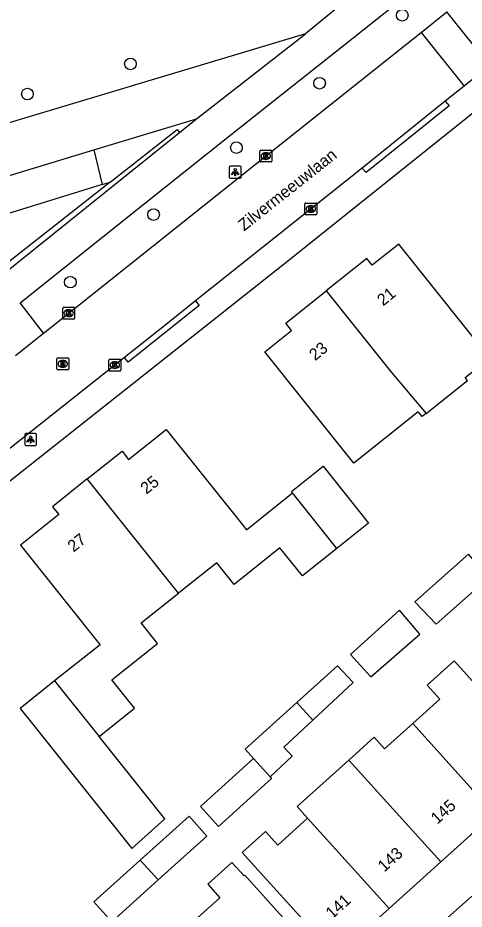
# Model space of a CAD drawing. Extents: x 161772 to 163123, y 383092 to 383917.
# Drawn here: x 162665.1 to 162702.7, y 383567.7 to 383642.9 of the extents above; entities that cross this region are included whole.
import ezdxf

# ---------------------------------------------------------------- set-up
doc = ezdxf.new("R2010")
doc.units = 0
for name, color, linetype in [('IMGEO_Boom', 7, 'Continuous'), ('IMGEO_Groenvoorziening', 7, 'Continuous'), ('IMGEO_Haag', 7, 'Continuous'), ('IMGEO_Kolk', 7, 'Continuous'), ('IMGEO_Lichtpunt', 7, 'Continuous'), ('IMGEO_Openbare_ruimte_label', 7, 'Continuous'), ('IMGEO_Pand', 7, 'Continuous'), ('IMGEO_Pand_nummerreeks', 7, 'Continuous'), ('IMGEO_Rijbaan_lokaal_open', 7, 'Continuous'), ('IMGEO_Rioolput', 7, 'Continuous'), ('IMGEO_Voetpad_open', 7, 'Continuous')]:
    doc.layers.add(name, color=color, linetype=linetype)

msp = doc.modelspace()

# ---------------------------------------------------------------- linework, layer by layer
at = {"layer": 'IMGEO_Boom'}
for centre in [(162697.497, 383643.114), (162674.58, 383639.013), (162690.522, 383637.385), (162665.894, 383636.474), (162683.506, 383631.951), (162676.528, 383626.302), (162669.511, 383620.601)]:
    msp.add_circle(centre, 0.489, dxfattribs=at)
at = {"layer": 'IMGEO_Groenvoorziening'}
for points in [[(162671.488, 383631.764), (162672.208, 383628.835)], [(162672.208, 383628.835), (162648.943, 383621.628)], [(162672.208, 383628.835), (162672.858, 383629.037)]]:
    msp.add_lwpolyline(points, dxfattribs=at)
at = {"layer": 'IMGEO_Haag'}
for points in [[(162672.858, 383629.037), (162678.511, 383633.479), (162678.71, 383633.228)], [(162672.858, 383629.037), (162659.165, 383618.275), (162658.88, 383618.558), (162651.638, 383612.821), (162648.943, 383621.628)]]:
    msp.add_lwpolyline(points, dxfattribs=at)
at = {"layer": 'IMGEO_Kolk'}
for p, q in [((162685.488, 383630.813), (162685.488, 383631.665)), ((162685.563, 383631.739), (162686.415, 383631.739)), ((162685.976, 383631.519), (162686.001, 383631.519)), ((162686.489, 383631.665), (162686.489, 383630.813)), ((162686.415, 383630.739), (162685.563, 383630.739)), ((162685.999, 383630.959), (162685.974, 383630.959)), ((162689.29, 383626.352), (162689.29, 383627.204)), ((162689.365, 383627.278), (162690.217, 383627.278)), ((162689.778, 383627.058), (162689.803, 383627.058)), ((162690.291, 383627.204), (162690.291, 383626.352)), ((162690.217, 383626.278), (162689.365, 383626.278)), ((162689.801, 383626.498), (162689.776, 383626.498)), ((162668.871, 383617.562), (162668.871, 383618.414)), ((162668.946, 383618.488), (162669.798, 383618.488)), ((162669.359, 383618.268), (162669.384, 383618.268)), ((162669.872, 383618.414), (162669.872, 383617.562)), ((162669.382, 383617.708), (162669.357, 383617.708)), ((162669.798, 383617.488), (162668.946, 383617.488)), ((162672.765, 383613.179), (162672.765, 383614.031)), ((162672.84, 383614.105), (162673.692, 383614.105)), ((162673.253, 383613.885), (162673.278, 383613.885)), ((162673.766, 383614.031), (162673.766, 383613.179)), ((162673.692, 383613.105), (162672.84, 383613.105)), ((162673.276, 383613.325), (162673.251, 383613.325))]:
    msp.add_line(p, q, dxfattribs=at)
for points in [[(162685.488, 383630.813), (162685.488, 383631.665)], [(162685.563, 383631.739), (162686.415, 383631.739)], [(162685.809, 383631.439), (162685.932, 383631.439), (162685.932, 383631.288), (162686.062, 383631.439), (162686.226, 383631.439), (162686.08, 383631.288), (162686.233, 383631.039), (162686.081, 383631.039), (162685.996, 383631.203), (162685.932, 383631.136), (162685.932, 383631.039), (162685.809, 383631.039), (162685.809, 383631.439)], [(162686.489, 383631.665), (162686.489, 383630.813)], [(162686.415, 383630.739), (162685.563, 383630.739)], [(162689.29, 383626.352), (162689.29, 383627.204)], [(162689.365, 383627.278), (162690.217, 383627.278)], [(162689.611, 383626.978), (162689.734, 383626.978), (162689.734, 383626.827), (162689.864, 383626.978), (162690.028, 383626.978), (162689.882, 383626.827), (162690.035, 383626.578), (162689.883, 383626.578), (162689.798, 383626.742), (162689.734, 383626.675), (162689.734, 383626.578), (162689.611, 383626.578), (162689.611, 383626.978)], [(162690.291, 383627.204), (162690.291, 383626.352)], [(162690.217, 383626.278), (162689.365, 383626.278)], [(162668.871, 383617.562), (162668.871, 383618.414)], [(162668.946, 383618.488), (162669.798, 383618.488)], [(162669.872, 383618.414), (162669.872, 383617.562)], [(162669.192, 383618.188), (162669.315, 383618.188), (162669.315, 383618.037), (162669.445, 383618.188), (162669.609, 383618.188), (162669.463, 383618.037), (162669.616, 383617.788), (162669.464, 383617.788), (162669.379, 383617.952), (162669.315, 383617.885), (162669.315, 383617.788), (162669.192, 383617.788), (162669.192, 383618.188)], [(162669.798, 383617.488), (162668.946, 383617.488)], [(162672.765, 383613.179), (162672.765, 383614.031)], [(162672.84, 383614.105), (162673.692, 383614.105)], [(162673.086, 383613.805), (162673.209, 383613.805), (162673.209, 383613.654), (162673.339, 383613.805), (162673.503, 383613.805), (162673.357, 383613.654), (162673.51, 383613.405), (162673.358, 383613.405), (162673.273, 383613.569), (162673.209, 383613.502), (162673.209, 383613.405), (162673.086, 383613.405), (162673.086, 383613.805)], [(162673.766, 383614.031), (162673.766, 383613.179)], [(162673.692, 383613.105), (162672.84, 383613.105)]]:
    msp.add_lwpolyline(points, dxfattribs=at)
for centre, start, end in [((162685.565, 383631.663), 91.55205, 178.44795), ((162685.565, 383631.663), 91.55205, 178.44795), ((162686.413, 383631.663), 1.55205, 88.44795), ((162686.413, 383631.663), 1.55205, 88.44795), ((162685.565, 383630.815), 181.55205, 268.44795), ((162685.565, 383630.815), 181.55205, 268.44795), ((162686.413, 383630.815), 271.55205, 358.44795), ((162686.413, 383630.815), 271.55205, 358.44795), ((162689.367, 383627.202), 91.55205, 178.44795), ((162689.367, 383627.202), 91.55205, 178.44795), ((162690.215, 383627.202), 1.55205, 88.44795), ((162690.215, 383627.202), 1.55205, 88.44795), ((162689.367, 383626.354), 181.55205, 268.44795), ((162689.367, 383626.354), 181.55205, 268.44795), ((162690.215, 383626.354), 271.55205, 358.44795), ((162690.215, 383626.354), 271.55205, 358.44795), ((162668.948, 383618.412), 91.55205, 178.44795), ((162668.948, 383618.412), 91.55205, 178.44795), ((162669.796, 383618.412), 1.55205, 88.44795), ((162669.796, 383618.412), 1.55205, 88.44795), ((162668.948, 383617.564), 181.55205, 268.44795), ((162668.948, 383617.564), 181.55205, 268.44795), ((162669.796, 383617.564), 271.55205, 358.44795), ((162669.796, 383617.564), 271.55205, 358.44795), ((162672.842, 383614.029), 91.55205, 178.44795), ((162672.842, 383614.029), 91.55205, 178.44795), ((162673.69, 383614.029), 1.55205, 88.44795), ((162673.69, 383614.029), 1.55205, 88.44795), ((162672.842, 383613.181), 181.55205, 268.44795), ((162672.842, 383613.181), 181.55205, 268.44795), ((162673.69, 383613.181), 271.55205, 358.44795), ((162673.69, 383613.181), 271.55205, 358.44795)]:
    msp.add_arc(centre, 0.0765, start, end, dxfattribs=at)
for centre, major_axis, ratio, start_param, end_param in [((162685.975, 383631.239), (-0.387, 0.002), 0.722429, 4.712389, 7.853982), ((162686, 383631.239), (-0.39, 0.002), 0.717154, 1.570796, 4.712389), ((162689.777, 383626.778), (-0.387, 0.002), 0.722429, 4.712389, 7.853982), ((162689.802, 383626.778), (-0.39, 0.002), 0.717154, 1.570796, 4.712389), ((162669.358, 383617.988), (-0.387, 0.002), 0.722429, 4.712389, 7.853982), ((162669.383, 383617.988), (-0.39, 0.002), 0.717154, 1.570796, 4.712389), ((162673.252, 383613.605), (-0.387, 0.002), 0.722429, 4.712389, 7.853982), ((162673.277, 383613.605), (-0.39, 0.002), 0.717154, 1.570796, 4.712389)]:
    msp.add_ellipse(centre, major_axis=major_axis, ratio=ratio, start_param=start_param, end_param=end_param, dxfattribs=at)
at = {"layer": 'IMGEO_Lichtpunt'}
for p, q in [((162683.815, 383630.381), (162683.007, 383630.381)), ((162683.815, 383630.381), (162683.007, 383630.381)), ((162682.913, 383630.286), (162682.913, 383629.479)), ((162682.913, 383630.286), (162682.913, 383629.479)), ((162683.909, 383629.479), (162683.909, 383630.286)), ((162683.909, 383629.479), (162683.909, 383630.286)), ((162683.007, 383629.385), (162683.815, 383629.385)), ((162683.007, 383629.385), (162683.815, 383629.385)), ((162666.566, 383607.82), (162665.758, 383607.82)), ((162666.566, 383607.82), (162665.758, 383607.82)), ((162665.664, 383607.725), (162665.664, 383606.918)), ((162665.664, 383607.725), (162665.664, 383606.918)), ((162666.66, 383606.918), (162666.66, 383607.725)), ((162666.66, 383606.918), (162666.66, 383607.725)), ((162665.758, 383606.824), (162666.566, 383606.824)), ((162665.758, 383606.824), (162666.566, 383606.824))]:
    msp.add_line(p, q, dxfattribs=at)
for points in [[(162683.287, 383629.95), (162683.326, 383629.922), (162683.138, 383629.66), (162683.1, 383629.687), (162683.287, 383629.95)], [(162683.389, 383629.902), (162683.436, 383629.902), (162683.436, 383629.58), (162683.389, 383629.58), (162683.389, 383629.902)], [(162683.499, 383629.922), (162683.537, 383629.949), (162683.724, 383629.687), (162683.685, 383629.659), (162683.499, 383629.922)], [(162666.038, 383607.389), (162666.077, 383607.361), (162665.889, 383607.099), (162665.851, 383607.126), (162666.038, 383607.389)], [(162666.14, 383607.341), (162666.187, 383607.341), (162666.187, 383607.019), (162666.14, 383607.019), (162666.14, 383607.341)], [(162666.25, 383607.361), (162666.288, 383607.388), (162666.475, 383607.126), (162666.436, 383607.098), (162666.25, 383607.361)]]:
    msp.add_lwpolyline(points, dxfattribs=at)
for centre in [(162683.412, 383630.084), (162666.163, 383607.523)]:
    msp.add_circle(centre, 0.0994, dxfattribs=at)
for centre, start, end in [((162683.007, 383630.286), 90, 180), ((162683.007, 383630.286), 90, 180), ((162683.815, 383630.286), 0, 90), ((162683.815, 383630.286), 0, 90), ((162683.007, 383629.479), 180, 270), ((162683.007, 383629.479), 180, 270), ((162683.815, 383629.479), 270, 0), ((162683.815, 383629.479), 270, 360), ((162665.758, 383607.725), 90, 180), ((162665.758, 383607.725), 90, 180), ((162666.566, 383607.725), 0, 90), ((162666.566, 383607.725), 0, 90), ((162665.758, 383606.918), 180, 270), ((162665.758, 383606.918), 180, 270), ((162666.566, 383606.918), 270, 0), ((162666.566, 383606.918), 270, 360)]:
    msp.add_arc(centre, 0.0946, start, end, dxfattribs=at)
at = {"layer": 'IMGEO_Pand'}
for points in [[(162699.5, 383609.522), (162702.994, 383612.309), (162702.801, 383612.552), (162704.869, 383614.201), (162700.315, 383619.91), (162697.198, 383623.819), (162694.961, 383622.035), (162694.508, 383622.602), (162691.089, 383619.875)], [(162699.5, 383609.522), (162699.169, 383609.258), (162698.841, 383609.669), (162693.401, 383605.33), (162689.023, 383610.82), (162685.905, 383614.729), (162688.164, 383616.531), (162687.671, 383617.149), (162691.089, 383619.875)], [(162691.089, 383619.875), (162696.576, 383612.99), (162699.5, 383609.522)], [(162670.933, 383604.001), (162673.871, 383606.345), (162674.424, 383605.651), (162677.598, 383608.183), (162684.055, 383600.086), (162684.348, 383599.715), (162688.246, 383602.823)], [(162688.246, 383602.823), (162688.146, 383602.948), (162690.815, 383605.076), (162694.653, 383600.264), (162691.984, 383598.136)], [(162670.933, 383604.001), (162667.996, 383601.659), (162668.533, 383600.986), (162665.313, 383598.418), (162671.756, 383590.339), (162672.015, 383590.01), (162668.189, 383586.96)], [(162678.624, 383594.357), (162670.933, 383604.001)], [(162691.984, 383598.136), (162688.246, 383602.823)], [(162691.984, 383598.136), (162689.071, 383595.813), (162687.18, 383598.184), (162683.312, 383595.1), (162681.852, 383596.931), (162678.624, 383594.357)], [(162698.554, 383593.623), (162700.362, 383591.738), (162704.799, 383595.691), (162703.063, 383597.64), (162698.554, 383593.623)], [(162671.933, 383582.264), (162674.922, 383584.647), (162673.011, 383587.044), (162676.861, 383590.114), (162675.478, 383591.848), (162678.624, 383594.357)], [(162693.12, 383589.196), (162694.834, 383587.297), (162698.965, 383590.915), (162697.248, 383592.922), (162693.12, 383589.196)], [(162689.947, 383583.652), (162693.34, 383586.832), (162692.038, 383588.221), (162688.61, 383585.134)], [(162709.795, 383579.86), (162706.446, 383583.573), (162702.922, 383587.479), (162701.855, 383588.661), (162699.582, 383586.608), (162700.648, 383585.427), (162698.375, 383583.374)], [(162668.189, 383586.96), (162665.286, 383584.645), (162666.325, 383583.342), (162674.706, 383572.83), (162677.472, 383575.319), (162671.933, 383582.264)], [(162668.189, 383586.96), (162671.678, 383582.584), (162671.933, 383582.264)], [(162688.61, 383585.134), (162684.247, 383581.204), (162684.96, 383580.414)], [(162689.947, 383583.652), (162688.61, 383585.134)], [(162686.361, 383578.863), (162688.218, 383580.603), (162687.505, 383581.364), (162689.947, 383583.652)], [(162698.375, 383583.374), (162696.002, 383581.232), (162695.118, 383582.211), (162692.986, 383580.286)], [(162698.375, 383583.374), (162705.248, 383575.759)], [(162686.361, 383578.863), (162686.477, 383578.734), (162681.989, 383574.681), (162680.472, 383576.361), (162684.96, 383580.414)], [(162684.96, 383580.414), (162686.361, 383578.863)], [(162692.986, 383580.286), (162688.629, 383576.351), (162689.511, 383575.374)], [(162692.986, 383580.286), (162700.741, 383571.693)], [(162676.913, 383570.166), (162681.026, 383573.874), (162679.516, 383575.549), (162675.403, 383571.841)], [(162705.248, 383575.759), (162700.741, 383571.693)], [(162689.511, 383575.374), (162687.005, 383573.112), (162685.973, 383574.256), (162684.01, 383572.485), (162685.042, 383571.34), (162688.561, 383567.438), (162691.91, 383563.726)], [(162696.385, 383567.762), (162689.511, 383575.374)], [(162676.913, 383570.166), (162673, 383566.638), (162671.49, 383568.313), (162675.403, 383571.841)], [(162675.403, 383571.841), (162676.913, 383570.166)], [(162691.055, 383562.975), (162687.706, 383566.688), (162684.217, 383570.558), (162684.159, 383570.506), (162683.135, 383571.644), (162681.095, 383569.808), (162682.12, 383568.67), (162679.703, 383566.495)], [(162700.741, 383571.693), (162696.385, 383567.762)], [(162696.385, 383567.762), (162691.91, 383563.726)]]:
    msp.add_lwpolyline(points, dxfattribs=at)
at = {"layer": 'IMGEO_Rijbaan_lokaal_open'}
for points in [[(162699.072, 383641.668), (162701.248, 383643.417)], [(162704.881, 383638.881), (162701.248, 383643.417)], [(162667.251, 383616.292), (162668.042, 383616.925), (162684.957, 383630.414), (162697.732, 383640.591), (162699.072, 383641.668)], [(162699.072, 383641.668), (162702.704, 383637.132)], [(162704.881, 383638.881), (162702.704, 383637.132)], [(162702.704, 383637.132), (162701.12, 383635.86)], [(162701.12, 383635.86), (162694.111, 383630.231)], [(162694.111, 383630.231), (162680.068, 383619.013)], [(162680.068, 383619.013), (162677.858, 383617.247), (162674.08, 383614.252)], [(162664.891, 383614.403), (162667.251, 383616.292)], [(162674.08, 383614.252), (162661.946, 383604.633), (162660.209, 383603.237)]]:
    msp.add_lwpolyline(points, dxfattribs=at)
at = {"layer": 'IMGEO_Rioolput'}
for p, q in [((162668.373, 383613.284), (162668.373, 383614.136)), ((162668.448, 383614.21), (162669.3, 383614.21)), ((162668.861, 383613.99), (162668.886, 383613.99)), ((162669.374, 383614.136), (162669.374, 383613.284)), ((162669.3, 383613.21), (162668.448, 383613.21)), ((162668.884, 383613.43), (162668.859, 383613.43))]:
    msp.add_line(p, q, dxfattribs=at)
for points in [[(162668.373, 383613.284), (162668.373, 383614.136)], [(162668.448, 383614.21), (162669.3, 383614.21)], [(162668.962, 383613.908), (162668.71, 383613.91), (162668.71, 383613.51)], [(162668.888, 383613.829), (162668.834, 383613.829), (162668.834, 383613.748)], [(162669.374, 383614.136), (162669.374, 383613.284)], [(162669.3, 383613.21), (162668.448, 383613.21)], [(162668.71, 383613.51), (162668.834, 383613.51), (162668.834, 383613.672), (162668.845, 383613.672)], [(162668.834, 383613.748), (162668.886, 383613.748)], [(162668.892, 383613.643), (162668.963, 383613.51), (162669.103, 383613.51), (162669.038, 383613.636)]]:
    msp.add_lwpolyline(points, dxfattribs=at)
for centre, radius, start, end in [((162668.45, 383614.134), 0.0765, 91.55205, 178.44795), ((162668.45, 383614.134), 0.0765, 91.55205, 178.44795), ((162668.894, 383613.733), 0.0964, 77.00612, 93.18647), ((162668.908, 383613.79), 0.0378, 276.66336, 79.67722), ((162668.961, 383613.798), 0.109, 350.36119, 89.41601), ((162668.959, 383613.798), 0.112, 277.58423, 350.98172), ((162669.298, 383614.134), 0.0765, 1.55205, 88.44795), ((162669.298, 383614.134), 0.0765, 1.55205, 88.44795), ((162668.45, 383613.286), 0.0765, 181.55205, 268.44795), ((162668.45, 383613.286), 0.0765, 181.55205, 268.44795), ((162668.844, 383613.619), 0.0533, 26.02933, 88.69889), ((162668.87, 383613.937), 0.19, 274.7715, 282.96867), ((162668.943, 383613.583), 0.108, 29.51342, 73.79051), ((162669.298, 383613.286), 0.0765, 271.55205, 358.44795), ((162669.298, 383613.286), 0.0765, 271.55205, 358.44795)]:
    msp.add_arc(centre, radius, start, end, dxfattribs=at)
for centre, major_axis, ratio, start_param, end_param in [((162668.86, 383613.71), (-0.387, 0.002), 0.722429, 4.712389, 7.853982), ((162668.885, 383613.71), (-0.39, 0.002), 0.717154, 1.570796, 4.712389)]:
    msp.add_ellipse(centre, major_axis=major_axis, ratio=ratio, start_param=start_param, end_param=end_param, dxfattribs=at)
at = {"layer": 'IMGEO_Voetpad_open'}
for points in [[(162624.721, 383572.388), (162687.563, 383622.167), (162778.983, 383695.388), (162783.083, 383695.752)], [(162710.846, 383658.743), (162699.148, 383649.621), (162689.341, 383641.552)], [(162667.251, 383616.292), (162665.282, 383618.845), (162675.59, 383627.092), (162683.07, 383633.05), (162692.535, 383640.57), (162701.507, 383647.712), (162711.694, 383655.8), (162712.694, 383652.602)], [(162689.341, 383641.552), (162650.206, 383629.785), (162635.239, 383625.167), (162631.465, 383624.003), (162627.261, 383622.706), (162626.016, 383626.892)], [(162680.147, 383634.381), (162689.341, 383641.552)], [(162701.12, 383635.86), (162701.434, 383635.472), (162694.454, 383629.866), (162694.111, 383630.231)], [(162671.488, 383631.764), (162680.147, 383634.381)], [(162678.71, 383633.228), (162680.147, 383634.381)], [(162651.381, 383611.952), (162658.791, 383617.831), (162659.1, 383617.49), (162673.883, 383629.354), (162678.71, 383633.228)], [(162648.064, 383624.499), (162661.565, 383628.766), (162671.488, 383631.764)], [(162680.068, 383619.013), (162680.38, 383618.623), (162674.392, 383613.862), (162674.08, 383614.252)], [(162686.898, 383554.157), (162703.359, 383568.789)]]:
    msp.add_lwpolyline(points, dxfattribs=at)

# ---------------------------------------------------------------- texts
at = {"layer": 'IMGEO_Openbare_ruimte_label'}
msp.add_text('Zilvermeeuwlaan', height=1, rotation=38.46295, dxfattribs=at).set_placement((162684.159, 383624.87))
at = {"layer": 'IMGEO_Pand_nummerreeks'}
for s, rotation, p in [('21', 38.8314, (162695.875, 383618.544)), ('23', 38.8314, (162690.141, 383613.928)), ('25', 38.47985, (162675.921, 383602.661)), ('27', 38.4802, (162669.778, 383597.778)), ('145', 42.0551, (162700.445, 383574.819)), ('143', 42.0551, (162695.973, 383570.786)), ('141', 42.0551, (162691.587, 383566.829))]:
    msp.add_text(s, height=1, rotation=rotation, dxfattribs=at).set_placement(p)

doc.saveas('drawing.dxf')
